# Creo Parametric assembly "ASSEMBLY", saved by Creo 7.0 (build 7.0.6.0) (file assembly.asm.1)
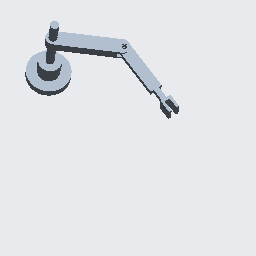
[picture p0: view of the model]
Units: millimeter Newton Second (mmNs); MM, TONNE, SECS

Created from: XX_MMNS_ASM_DESIGN_ABS.ASM

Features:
  1. datum plane "ASM_RIGHT"
  2. datum plane "ASM_TOP"
  3. datum plane "ASM_FRONT"
  4. coordinate system
  5. component "BASE_10_1"
  6. component "COLUMN_10_2"
  7. component "LINK_10_3"
  8. component "LINK_10_4"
